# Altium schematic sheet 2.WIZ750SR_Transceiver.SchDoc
size A4; DrawnBy: Edward; Organization: WIZnet Co., Ltd.; Address1: 5F, Humax Village; Address2: Hwangseaul-ro, Bundang-Gu; Address3: Seongnam-Si, Gyeonggi-Do; Address4: South Korea; Team: CS
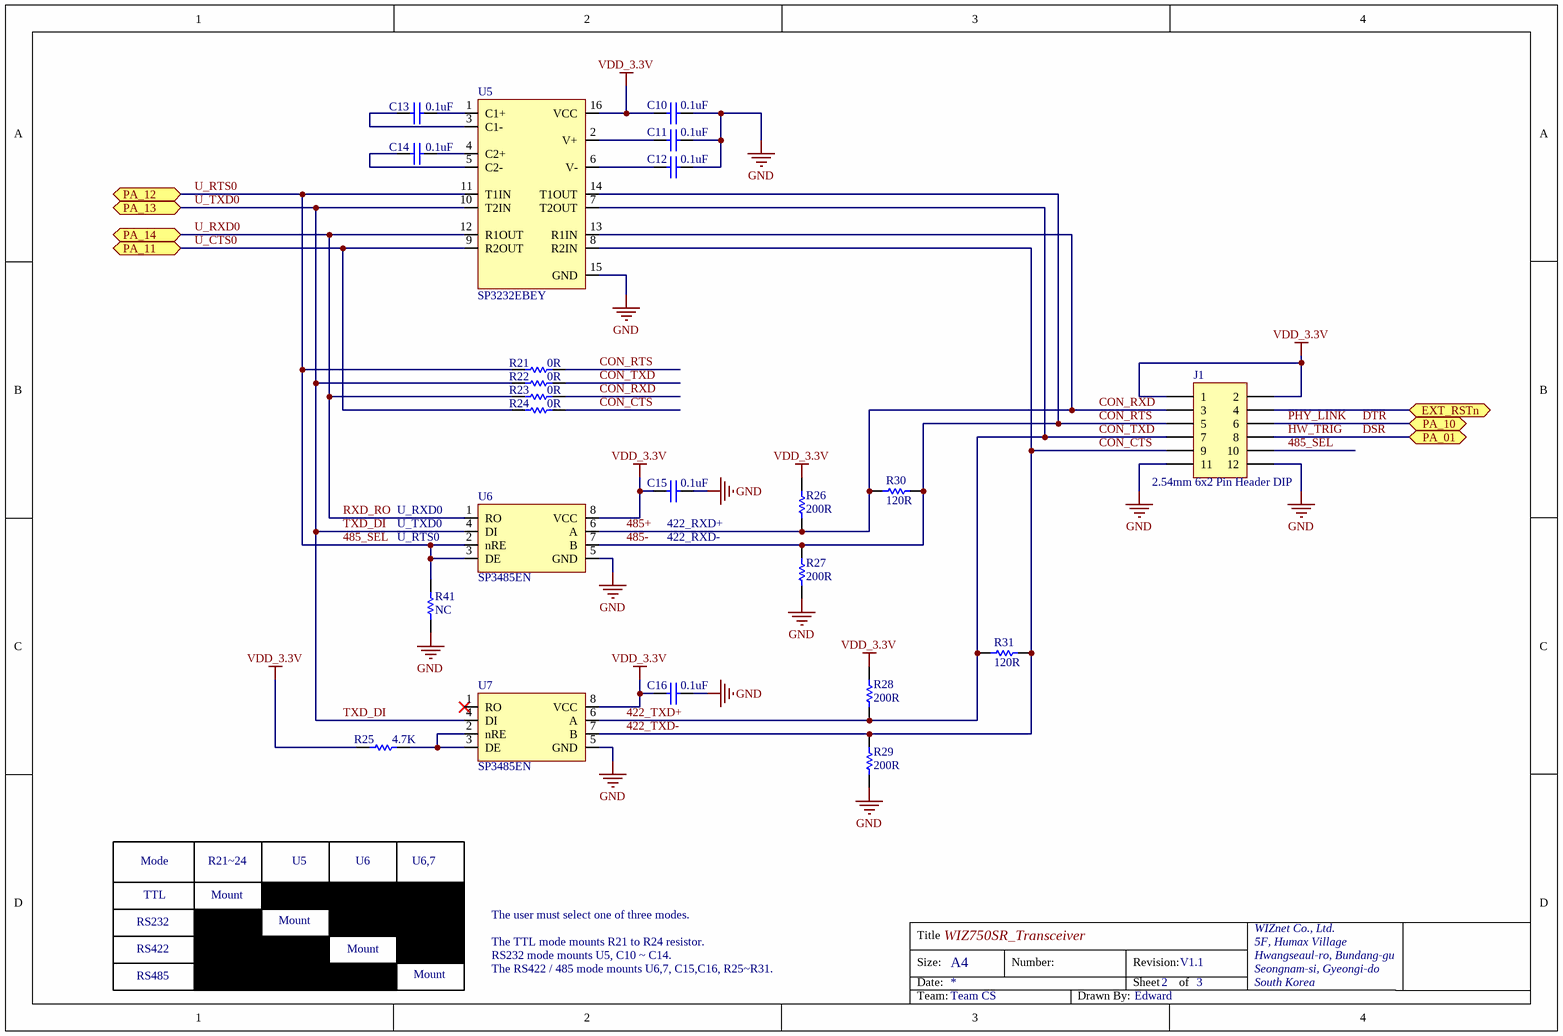
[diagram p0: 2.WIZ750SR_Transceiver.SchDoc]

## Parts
C10  0.1uF  [CAP-0402]
C11  0.1uF  [CAP-0402]
C12  0.1uF  [CAP-0402]
C13  0.1uF  [CAP-0402]
C14  0.1uF  [CAP-0402]
C15  0.1uF  [CAP-0402]
C16  0.1uF  [CAP-0402]
J1  2.54mm 6x2 Pin Header DIP  [IDC-2X6]
R21  0R  [RES-0402]
R22  0R  [RES-0402]
R23  0R  [RES-0402]
R24  0R  [RES-0402]
R25  4.7K  [RES-0402]
R26  200R  [RES-0402]
R27  200R  [RES-0402]
R28  200R  [RES-0402]
R29  200R  [RES-0402]
R30  120R  [RES-0402]
R31  120R  [RES-0402]
R41  NC  [RES-0402]
U5  SP3232EBEY  [TSSOP16(0.65/6.4)]
U6  SP3485EN  [SO-08]
U7  SP3485EN  [SO-08]

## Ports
EXT_RSTn, PA_01, PA_10, PA_11, PA_12, PA_13, PA_14

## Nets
GND: C10.1 C11.1 C12.1 C15.1 C16.1 J1.11 J1.12 R27.2 R29.2 R41.2 U5.15(GND) U6.5(GND) U7.5(GND)
VDD_3.3V: C10.2 C15.2 C16.2 J1.1 J1.2 R25.2 R26.1 R28.1 U5.16(VCC) U6.8(VCC) U7.8(VCC)
422_TXD+: J1.7 R22.1 R28.2 R31.2 U5.7(T2OUT) U7.6(A)  [also labelled CON_TXD]
422_TXD-: J1.9 R24.1 R29.1 R31.1 U5.8(R2IN) U7.7(B)  [also labelled CON_CTS]
485+: J1.3 R23.1 R26.2 R30.2 U5.13(R1IN) U6.6(A)  [also labelled CON_RXD]
485-: J1.5 R21.1 R27.1 R30.1 U5.14(T1OUT) U6.7(B)  [also labelled CON_RTS]
485_SEL: J1.10 R21.2 R41.1 U5.11(T1IN) U6.2(nRE) U6.3(DE) ; port PA_12  [also labelled U_RTS0]
DSR: J1.8 ; port PA_01  [also labelled HW_TRIG]
DTR: J1.6 ; port PA_10  [also labelled PHY_LINK]
EXT_RSTn: J1.4 ; port EXT_RSTn
RXD_RO: R23.2 U5.12(R1OUT) U6.1(RO) ; port PA_14  [also labelled U_RXD0]
TXD_DI: R22.2 U5.10(T2IN) U6.4(DI) U7.4(DI) ; port PA_13  [also labelled U_TXD0]
U_CTS0: R24.2 U5.9(R2OUT) ; port PA_11
NetC11_2: C11.2 U5.2(V+)
NetC12_2: C12.2 U5.6(V-)
NetC13_1: C13.1 U5.1(C1+)
NetC13_2: C13.2 U5.3(C1-)
NetC14_1: C14.1 U5.4(C2+)
NetC14_2: C14.2 U5.5(C2-)
NetR25_1: R25.1 U7.2(nRE) U7.3(DE)

Not connected (* = marked no-connect by the designer): U7 1(RO)*

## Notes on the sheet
- (near U6) U_RXD0
- U_TXD0
- U_RTS0
- (near C15) 422_RXD+
- (near C15) 422_RXD-
- RS232
- Mode
- TTL
- R21|4
- Mount
- U5
- U6
- U6,7
- The user must select one of three modes.
- RS422
- RS485
- The TTL mode mounts R21 to R24 resistor.
- RS232 mode mounts U5, C10 ~ C14.
- The RS422 / 485 mode mounts U6,7, C15,C16, R25~R31.
- Title
- Size:
- Date:
- WIZ750SR_Transceiver
- A4
- Number:
- Revision:
- Sheet
- 2
- of
- V1.1
- 3
- WIZnet Co., Ltd.
- 5F, Humax Village
- Hwangseaul-ro, Bundang-gu
- Seongnam-si, Gyeongi-do
- South Korea
- Team:
- Team CS
- Drawn By:
- Edward

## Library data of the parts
C10-C16 = CAP-0402: Ceramic CAP 0402(1005)
J1 = Header 6X2: Header, 6-Pin, Dual row
R21-R31 R41 = RES-0402
U5 = SP3232EBEY: True +3.0V to +5.5V RS-232 Transceivers TSSOP16
U6 U7 = SP3485EN: RS485 Transceiver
